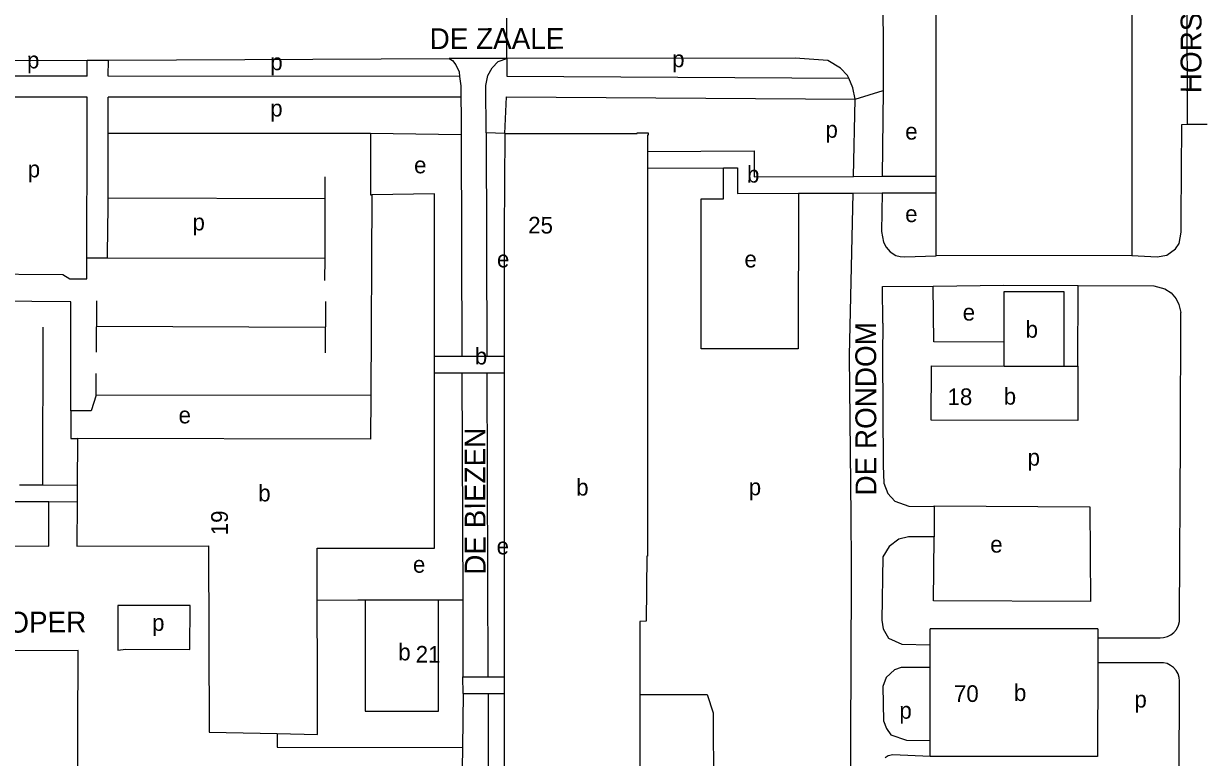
# Model space of a CAD drawing. Extents: x 161494 to 163033, y 383688 to 384862.
# Drawn here: x 162234.2 to 162517.1, y 384203.6 to 384379.7 of the extents above; entities that cross this region are included whole.
import ezdxf

# ---------------------------------------------------------------- set-up
doc = ezdxf.new("R2010")
doc.units = 0
for name, color, linetype in [('BLT_Basislijn', 7, 'Continuous'), ('BLT_Bebouwing', 7, 'Continuous'), ('BLT_Centroide', 7, 'Continuous'), ('BLT_Huisnummer', 7, 'Continuous'), ('BLT_Huisnummer_reeks', 7, 'Continuous'), ('BLT_Onderdoorgang_en_onderverdeling', 7, 'Continuous'), ('BLT_Straatnaam', 7, 'Continuous'), ('BLT_Vlakafsluiter', 7, 'Continuous')]:
    doc.layers.add(name, color=color, linetype=linetype)

msp = doc.modelspace()

# ---------------------------------------------------------------- linework, layer by layer
at = {"layer": 'BLT_Basislijn'}
for p, q in [((162513.52, 384355.52), (162513.36, 384436.68)), ((162217.82, 384370.78), (162249.53, 384370.93)), ((162249.53, 384370.93), (162254.59, 384370.95)), ((162249.53, 384367.05), (162249.53, 384370.93)), ((162254.59, 384370.95), (162336.35, 384371.32)), ((162249.53, 384367.05), (162217.81, 384367.06)), ((162338.88, 384367.02), (162254.58, 384367.05)), ((162249.53, 384362.05), (162217.8, 384362.06)), ((162249.54, 384353.4), (162249.53, 384362.05)), ((162339.19, 384362.02), (162254.56, 384362.05)), ((162440.51, 384363.61), (162440.28, 384343.04)), ((162254.53, 384337.79), (162254.53, 384353.4)), ((162317.45, 384353.4), (162339.22, 384353.05)), ((162349.71, 384353.29), (162345.22, 384353.49)), ((162513.52, 384355.52), (162518.24, 384355.54)), ((162306.63, 384337.67), (162306.64, 384342.93)), ((162440.23, 384339.04), (162440.13, 384329.77)), ((162306.63, 384337.67), (162254.53, 384337.79)), ((162306.59, 384323.37), (162306.63, 384337.67)), ((162249.42, 384323.47), (162254.41, 384323.46)), ((162254.41, 384323.46), (162306.59, 384323.37)), ((162306.57, 384318.07), (162306.59, 384323.37)), ((162452.49, 384316.65), (162469.49, 384316.89)), ((162469.49, 384316.89), (162487.28, 384316.81)), ((162487.21, 384297.46), (162487.28, 384316.81)), ((162251.77, 384313.16), (162251.63, 384300.82)), ((162306.67, 384313.01), (162306.62, 384300.7)), ((162238.83, 384306.82), (162238.76, 384268.88)), ((162251.75, 384307.07), (162306.64, 384306.85)), ((162251.67, 384290.52), (162251.66, 384295.74)), ((162317.54, 384290.46), (162251.67, 384290.52)), ((162432.89, 384249.86), (162432.79, 384261.36)), ((162333.84, 384241.39), (162339.62, 384241.37)), ((162339.7, 384218.92), (162339.68, 384222.92)), ((162339.7, 384218.92), (162339.55, 384205.93)), ((162339.55, 384205.93), (162339.49, 384200.93))]:
    msp.add_line(p, q, dxfattribs=at)
for points in [[(162513.36, 384436.68), (162450.09, 384436.43), (162446.77, 384436.05), (162445.01, 384435.32), (162443.54, 384434.13), (162442.46, 384432.84), (162440.96, 384430.36), (162440.4, 384428.46), (162440.34, 384425.23), (162440.51, 384363.61)], [(162254.58, 384367.05), (162254.59, 384370.95)], [(162336.35, 384371.32), (162337.13, 384370.82), (162337.97, 384369.82), (162338.74, 384368.08), (162338.88, 384367.02)], [(162345.22, 384353.49), (162345.18, 384364.81), (162345.62, 384367.22), (162346.68, 384369.05), (162348.12, 384370.6), (162350.2, 384371.34)], [(162350.2, 384371.34), (162350.17, 384367.11), (162432.24, 384366.56)], [(162432.24, 384366.56), (162431.93, 384367.26), (162430.29, 384368.99), (162427.22, 384370.83), (162419.37, 384371.4), (162350.2, 384371.34)], [(162338.88, 384367.02), (162339.18, 384364.78), (162339.19, 384362.02)], [(162433.8, 384361.54), (162433.26, 384364.29), (162432.24, 384366.56)], [(162217.8, 384362.06), (162217.74, 384324.93), (162218.77, 384321.83), (162219.2, 384320.92), (162219.82, 384320.28), (162220.55, 384319.86), (162221.38, 384319.65), (162222.38, 384319.64), (162243.64, 384319.46), (162245.34, 384318.42), (162249.4, 384318.43), (162249.42, 384323.47)], [(162254.53, 384353.4), (162254.54, 384355.45), (162254.56, 384361.14), (162254.56, 384362.05)], [(162339.19, 384362.02), (162339.21, 384357.3)], [(162349.71, 384353.29), (162350.14, 384362.11), (162433.8, 384361.54)], [(162433.39, 384343.01), (162433.8, 384361.54)], [(162339.21, 384357.3), (162339.22, 384353.05)], [(162249.42, 384323.47), (162249.54, 384353.4)], [(162254.53, 384353.4), (162317.45, 384353.4)], [(162317.45, 384353.4), (162317.45, 384338.6), (162317.77, 384338.6)], [(162339.22, 384353.05), (162339.43, 384299.89)], [(162345.22, 384353.49), (162345.43, 384299.89)], [(162512.02, 384333.07), (162512.15, 384355.5), (162513.52, 384355.52)], [(162420.16, 384338.96), (162420.11, 384301.62), (162396.87, 384301.62), (162396.87, 384337.61), (162402.2, 384337.61), (162402.2, 384345.09)], [(162432.79, 384261.36), (162432.45, 384300), (162433.3, 384339.01)], [(162254.41, 384323.46), (162254.41, 384324.4), (162254.54, 384335.77), (162254.53, 384337.79)], [(162500.18, 384324.01), (162506.23, 384323.75), (162508.56, 384324.15), (162510.68, 384325.62), (162511.51, 384326.91), (162512.01, 384329.64), (162512.02, 384333.07)], [(162440.13, 384329.77), (162440.62, 384327.25), (162441.24, 384326), (162442.22, 384324.9), (162443.51, 384324.05), (162444.56, 384323.78), (162445.62, 384323.68), (162453.22, 384323.99)], [(162440.43, 384307.78), (162440.38, 384316.57), (162452.49, 384316.65)], [(162469.5, 384303.26), (162452.64, 384303.29), (162452.49, 384316.65)], [(162487.28, 384316.81), (162505.47, 384316.72), (162508.1, 384316.07), (162509.6, 384315.05), (162510.83, 384313.62), (162511.47, 384312.28), (162511.94, 384310.33)], [(162245.59, 384286.75), (162245.56, 384312.93), (162217.49, 384313.17), (162217.33, 384268.95)], [(162440.43, 384307.78), (162440.33, 384300), (162440.48, 384273.61), (162440.66, 384269.36), (162441.64, 384266.92), (162443.3, 384265.04), (162446.65, 384263.9), (162452.75, 384263.78)], [(162491.98, 384232.3), (162506.96, 384232.31), (162507.79, 384232.35), (162508.72, 384232.58), (162509.52, 384232.97), (162510.28, 384233.58), (162510.88, 384234.31), (162511.38, 384235.31), (162511.61, 384236.22), (162511.62, 384237.2), (162511.85, 384280.09), (162511.94, 384310.33)], [(162339.44, 384295.89), (162339.62, 384241.37)], [(162345.44, 384295.89), (162345.68, 384222.91)], [(162251.67, 384290.52), (162250.46, 384286.74), (162245.59, 384286.75)], [(162245.59, 384286.75), (162245.57, 384280.1), (162247.17, 384280.09)], [(162217.54, 384264.95), (162217.51, 384254.43), (162240.28, 384254.3), (162240.29, 384264.88)], [(162452.75, 384263.78), (162452.75, 384263.98), (162490.07, 384263.73), (162490.25, 384240.96)], [(162452.75, 384263.78), (162452.75, 384256.54)], [(162452.75, 384256.54), (162446.58, 384256.5), (162444.29, 384255.94), (162441.96, 384254.19), (162440.43, 384251.74), (162440.18, 384236.49), (162440.53, 384234.46), (162441.8, 384232.23), (162444.99, 384230.72), (162451.8, 384230.63)], [(162490.25, 384240.96), (162452.57, 384241.16), (162452.75, 384256.34), (162452.75, 384256.54)], [(162393.39, 384178.59), (162418.62, 384178.59), (162422.93, 384178.75), (162424.04, 384179.07), (162427.66, 384180.76), (162429.39, 384182.25), (162431.25, 384184.79), (162432.65, 384188.67), (162432.92, 384246.22), (162432.89, 384249.86)], [(162304.71, 384241.34), (162314.49, 384241.43), (162316.21, 384241.43)], [(162339.62, 384241.37), (162339.68, 384222.92)], [(162247.21, 384191.05), (162247.31, 384229.25), (162106.92, 384229), (162106.81, 384205.82), (162098.37, 384205.81), (162098.37, 384197.75), (162041.94, 384197.72), (162041.92, 384191.05), (162247.21, 384191.05)], [(162511.51, 384198.35), (162511.63, 384221.97), (162511.55, 384222.76), (162511.29, 384223.63), (162510.83, 384224.47), (162510.18, 384225.17), (162509.48, 384225.66), (162508.64, 384226.08), (162507.76, 384226.28), (162506.98, 384226.3), (162491.98, 384226.29)], [(162451.79, 384225.19), (162444.83, 384225.15), (162443.23, 384224.59), (162441.23, 384222.77), (162440.45, 384220.58), (162440.61, 384212.33), (162441.27, 384210.49), (162442.34, 384209.02), (162446.1, 384207.72), (162451.78, 384207.64)], [(162345.7, 384218.91), (162345.81, 384183.55), (162346.45, 384181.61), (162348.03, 384179.98), (162349.96, 384178.59)], [(162382.1, 384218.67), (162398.31, 384218.7), (162399.75, 384214.3), (162399.76, 384196.07), (162397.26, 384193.6), (162394.39, 384189.44), (162393.3, 384184.07), (162393.39, 384178.59)], [(162295.07, 384209.3), (162295.06, 384206.01), (162339.55, 384205.93)], [(162451.77, 384203.8), (162442.8, 384204.22), (162441.69, 384203.97), (162440.99, 384203.51)]]:
    msp.add_lwpolyline(points, dxfattribs=at)
msp.add_lwpolyline([(162256.89, 384240.06), (162256.87, 384229.29), (162258.77, 384229.53), (162274.1, 384229.51), (162274.21, 384240.02)], close=True, dxfattribs=at)
at = {"layer": 'BLT_Bebouwing'}
for p, q in [((162500.18, 384324.01), (162453.22, 384323.99)), ((162483.85, 384315.42), (162483.85, 384311.94)), ((162483.85, 384311.94), (162483.84, 384297.46)), ((162469.5, 384297.48), (162469.5, 384303.26)), ((162332.85, 384299.9), (162339.43, 384299.89)), ((162339.43, 384299.89), (162345.43, 384299.89)), ((162345.43, 384299.89), (162349.59, 384299.88)), ((162452.06, 384284.53), (162452.09, 384297.55)), ((162452.09, 384297.55), (162469.5, 384297.48)), ((162483.84, 384297.46), (162487.21, 384297.46)), ((162487.21, 384297.46), (162487.24, 384284.46)), ((162332.85, 384295.9), (162339.44, 384295.89)), ((162339.44, 384295.89), (162345.44, 384295.89)), ((162345.44, 384295.89), (162349.59, 384295.88)), ((162487.24, 384284.46), (162452.06, 384284.53)), ((162238.76, 384268.88), (162233.27, 384268.9)), ((162247.11, 384268.86), (162238.76, 384268.88)), ((162240.29, 384264.88), (162217.54, 384264.95)), ((162247.09, 384264.86), (162240.29, 384264.88)), ((162491.99, 384234.44), (162451.8, 384234.46)), ((162339.68, 384222.92), (162345.68, 384222.91)), ((162345.68, 384222.91), (162349.59, 384222.91)), ((162339.7, 384218.92), (162345.7, 384218.91)), ((162345.7, 384218.91), (162349.59, 384218.91))]:
    msp.add_line(p, q, dxfattribs=at)
for points in [[(162453.23, 384343.09), (162453.29, 384429.34), (162500.19, 384429.6), (162500.18, 384324.01)], [(162349.71, 384353.29), (162349.6, 384329.63), (162349.59, 384299.88)], [(162349.71, 384353.29), (162381.47, 384353.28), (162381.47, 384353.44), (162384.1, 384353.45), (162384.1, 384352.94), (162383.95, 384352.94), (162383.95, 384349.02)], [(162383.95, 384349.02), (162409.52, 384349.12), (162409.55, 384342.92), (162433.39, 384343.01)], [(162383.95, 384345.02), (162383.95, 384251.89), (162383.76, 384251.89), (162383.66, 384236.28), (162382.11, 384236.22), (162382.1, 384218.67)], [(162383.95, 384345.02), (162402.2, 384345.09)], [(162402.2, 384345.09), (162405.54, 384345.11), (162405.57, 384338.9), (162420.16, 384338.96)], [(162433.39, 384343.01), (162440.28, 384343.04)], [(162440.28, 384343.04), (162453.23, 384343.09)], [(162420.16, 384338.96), (162433.3, 384339.01)], [(162433.3, 384339.01), (162440.23, 384339.04)], [(162440.23, 384339.04), (162453.23, 384339.09)], [(162453.22, 384323.99), (162453.23, 384339.09)], [(162317.77, 384338.6), (162317.54, 384290.46)], [(162332.85, 384299.9), (162332.87, 384338.81), (162317.77, 384338.6)], [(162469.5, 384303.26), (162469.51, 384311.75), (162469.51, 384315.43)], [(162469.51, 384315.43), (162483.85, 384315.42)], [(162304.71, 384241.34), (162304.68, 384253.78), (162332.83, 384253.8), (162332.85, 384295.9)], [(162349.59, 384295.88), (162349.59, 384222.91)], [(162317.54, 384290.46), (162317.49, 384279.99), (162247.17, 384280.09)], [(162247.17, 384280.09), (162247.11, 384268.86)], [(162247.09, 384264.86), (162247.04, 384254.27), (162278.61, 384254.33), (162278.74, 384209.61), (162295.07, 384209.3)], [(162304.75, 384222.96), (162304.71, 384241.34)], [(162316.21, 384241.43), (162316.2, 384214.68), (162333.83, 384214.67), (162333.84, 384241.39)], [(162316.21, 384241.43), (162329.49, 384241.4), (162333.84, 384241.39)], [(162451.8, 384230.63), (162451.8, 384234.46)], [(162491.99, 384234.44), (162491.98, 384232.3)], [(162491.98, 384232.3), (162491.98, 384226.29)], [(162451.79, 384225.19), (162451.8, 384230.63)], [(162491.98, 384226.29), (162491.97, 384203.76), (162451.77, 384203.8)], [(162451.78, 384207.64), (162451.79, 384225.19)], [(162295.07, 384209.3), (162304.79, 384209.11), (162304.76, 384218.96)], [(162349.59, 384218.91), (162349.59, 384183.19)], [(162382.1, 384218.67), (162382.06, 384183.4)], [(162451.77, 384203.8), (162451.78, 384207.64)]]:
    msp.add_lwpolyline(points, dxfattribs=at)
at = {"layer": 'BLT_Onderdoorgang_en_onderverdeling'}
for p, q in [((162332.85, 384295.9), (162332.85, 384299.9)), ((162349.59, 384299.88), (162349.59, 384295.88)), ((162469.5, 384297.48), (162483.84, 384297.46)), ((162247.11, 384268.86), (162247.09, 384264.86)), ((162304.76, 384218.96), (162304.75, 384222.96)), ((162349.59, 384222.91), (162349.59, 384218.91))]:
    msp.add_line(p, q, dxfattribs=at)
for points in [[(162383.95, 384349.02), (162383.95, 384345.02)], [(162453.23, 384339.09), (162453.23, 384343.09)]]:
    msp.add_lwpolyline(points, dxfattribs=at)
at = {"layer": 'BLT_Vlakafsluiter'}
for p, q in [((162350.2, 384371.34), (162350.2, 384381)), ((162433.8, 384361.54), (162440.51, 384363.61))]:
    msp.add_line(p, q, dxfattribs=at)
for points in [[(162339.76, 384371.33), (162336.35, 384371.32)], [(162344.26, 384371.33), (162339.76, 384371.33)], [(162350.2, 384371.34), (162344.26, 384371.33)]]:
    msp.add_lwpolyline(points, dxfattribs=at)

# ---------------------------------------------------------------- texts
at = {"layer": 'BLT_Centroide'}
for s, p in [('p', (162235.07, 384368.94)), ('p', (162293.44, 384368.5)), ('p', (162389.87, 384369.21)), ('p', (162293.43, 384357.39)), ('p', (162426.66, 384352.3)), ('e', (162445.79, 384351.85)), ('p', (162235.24, 384342.79)), ('e', (162327.95, 384343.76)), ('b', (162407.83, 384341.53)), ('e', (162445.79, 384332.05)), ('p', (162274.78, 384330.05)), ('e', (162347.84, 384321.18)), ('e', (162407.22, 384321.17)), ('e', (162459.59, 384308.41)), ('b', (162474.68, 384304.31)), ('b', (162342.52, 384297.88)), ('b', (162469.44, 384288.24)), ('e', (162271.44, 384283.74)), ('p', (162475.16, 384273.6)), ('b', (162290.55, 384265.02)), ('b', (162366.84, 384266.42)), ('p', (162408.25, 384266.49)), ('e', (162347.75, 384252.3)), ('e', (162466.19, 384252.73)), ('e', (162327.68, 384247.9)), ('p', (162265.08, 384233.94)), ('b', (162324.15, 384226.87)), ('b', (162471.88, 384217.12)), ('p', (162500.79, 384215.54)), ('p', (162444.39, 384212.86))]:
    msp.add_text(s, height=4, dxfattribs=at).set_placement(p)
at = {"layer": 'BLT_Huisnummer'}
for s, rotation, p in [('19', 90.1214, (162283.27, 384256.89)), ('70', 359.9937, (162457.48, 384216.89))]:
    msp.add_text(s, height=4, rotation=rotation, dxfattribs=at).set_placement(p)
at = {"layer": 'BLT_Huisnummer_reeks'}
for s, rotation, p in [('25', 359.77, (162355.32, 384329.33)), ('18', 359.9937, (162455.94, 384288.14)), ('21', 359.77, (162328.32, 384226.34))]:
    msp.add_text(s, height=4, rotation=rotation, dxfattribs=at).set_placement(p)
at = {"layer": 'BLT_Straatnaam'}
for s, rotation, p in [('HORSTEN', 89.8991, (162516.86, 384363)), ('DE ZAALE', 0.1418, (162331.68, 384373.56)), ('DE RONDOM', 90.0852, (162438.87, 384266.44)), ('DE BIEZEN', 90.0852, (162345.1, 384247.42)), ('GROENE LOPER', 0.2472, (162195.8, 384233.37))]:
    msp.add_text(s, height=5, rotation=rotation, dxfattribs=at).set_placement(p)

doc.saveas('drawing.dxf')
